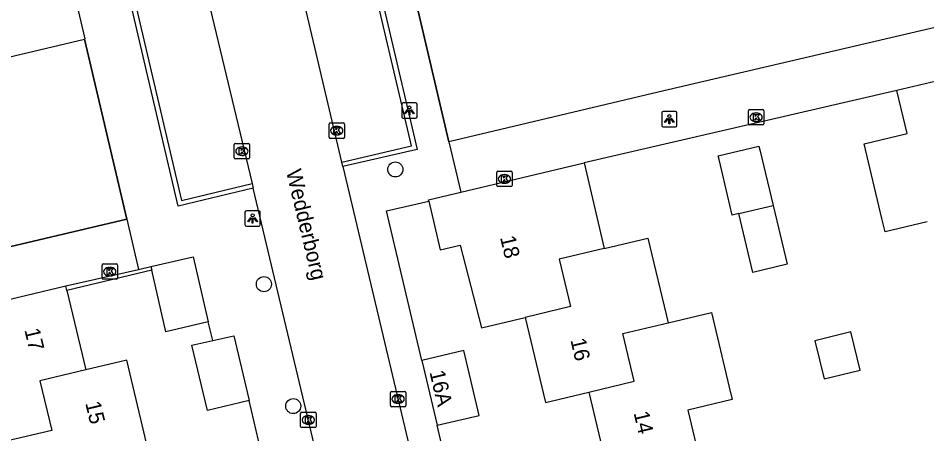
# Model space of a CAD drawing. Extents: x 158038 to 159242, y 380133 to 381214.
# Drawn here: x 158907 to 158966.1, y 380537.7 to 380564.7 of the extents above; entities that cross this region are included whole.
import ezdxf

# ---------------------------------------------------------------- set-up
doc = ezdxf.new("R2010")
doc.units = 0
for name, color, linetype in [('IMGEO_Boom', 7, 'Continuous'), ('IMGEO_Kolk', 7, 'Continuous'), ('IMGEO_Lichtpunt', 7, 'Continuous'), ('IMGEO_Muur', 7, 'Continuous'), ('IMGEO_Openbare_ruimte_label', 7, 'Continuous'), ('IMGEO_Pand', 7, 'Continuous'), ('IMGEO_Pand_nummerreeks', 7, 'Continuous'), ('IMGEO_Rijbaan_lokaal_open', 7, 'Continuous'), ('IMGEO_Voetpad_open', 7, 'Continuous')]:
    doc.layers.add(name, color=color, linetype=linetype)

msp = doc.modelspace()

# ---------------------------------------------------------------- linework, layer by layer
at = {"layer": 'IMGEO_Boom'}
for centre in [(158931.531, 380554.881), (158922.981, 380547.417), (158924.892, 380539.482)]:
    msp.add_circle(centre, 0.489, dxfattribs=at)
at = {"layer": 'IMGEO_Kolk'}
for p, q in [((158954.576, 380558.78), (158955.428, 380558.78)), ((158954.501, 380557.854), (158954.501, 380558.706)), ((158954.989, 380558.56), (158955.014, 380558.56)), ((158955.502, 380558.706), (158955.502, 380557.854)), ((158927.218, 380556.98), (158927.218, 380557.832)), ((158927.293, 380557.906), (158928.145, 380557.906)), ((158927.706, 380557.686), (158927.731, 380557.686)), ((158928.219, 380557.832), (158928.219, 380556.98)), ((158955.428, 380557.78), (158954.576, 380557.78)), ((158955.012, 380558), (158954.987, 380558)), ((158927.729, 380557.126), (158927.704, 380557.126)), ((158921.052, 380555.644), (158921.052, 380556.496)), ((158921.127, 380556.57), (158921.979, 380556.57)), ((158922.053, 380556.496), (158922.053, 380555.644)), ((158928.145, 380556.906), (158927.293, 380556.906)), ((158921.54, 380556.35), (158921.565, 380556.35)), ((158921.979, 380555.57), (158921.127, 380555.57)), ((158921.563, 380555.79), (158921.538, 380555.79)), ((158938.127, 380553.838), (158938.127, 380554.69)), ((158938.202, 380554.764), (158939.054, 380554.764)), ((158939.128, 380554.69), (158939.128, 380553.838)), ((158938.615, 380554.544), (158938.64, 380554.544)), ((158939.054, 380553.764), (158938.202, 380553.764)), ((158938.638, 380553.984), (158938.613, 380553.984)), ((158912.533, 380548.731), (158913.385, 380548.731)), ((158912.458, 380547.805), (158912.458, 380548.657)), ((158912.946, 380548.511), (158912.971, 380548.511)), ((158913.459, 380548.657), (158913.459, 380547.805)), ((158913.385, 380547.731), (158912.533, 380547.731)), ((158912.969, 380547.951), (158912.944, 380547.951)), ((158931.285, 380540.441), (158932.137, 380540.441)), ((158931.21, 380539.515), (158931.21, 380540.367)), ((158931.698, 380540.221), (158931.723, 380540.221)), ((158932.211, 380540.367), (158932.211, 380539.515)), ((158932.137, 380539.441), (158931.285, 380539.441)), ((158931.721, 380539.661), (158931.696, 380539.661)), ((158925.371, 380538.154), (158925.371, 380539.006)), ((158925.446, 380539.08), (158926.298, 380539.08)), ((158925.859, 380538.86), (158925.884, 380538.86)), ((158926.372, 380539.006), (158926.372, 380538.154)), ((158926.298, 380538.08), (158925.446, 380538.08)), ((158925.882, 380538.3), (158925.857, 380538.3))]:
    msp.add_line(p, q, dxfattribs=at)
for points in [[(158954.576, 380558.78), (158955.428, 380558.78)], [(158954.501, 380557.854), (158954.501, 380558.706)], [(158954.822, 380558.48), (158954.945, 380558.48), (158954.945, 380558.329), (158955.075, 380558.48), (158955.239, 380558.48), (158955.093, 380558.329), (158955.246, 380558.08), (158955.094, 380558.08), (158955.009, 380558.244), (158954.945, 380558.177), (158954.945, 380558.08), (158954.822, 380558.08), (158954.822, 380558.48)], [(158955.502, 380558.706), (158955.502, 380557.854)], [(158927.218, 380556.98), (158927.218, 380557.832)], [(158927.293, 380557.906), (158928.145, 380557.906)], [(158927.539, 380557.606), (158927.662, 380557.606), (158927.662, 380557.455), (158927.792, 380557.606), (158927.956, 380557.606), (158927.81, 380557.455), (158927.963, 380557.206), (158927.811, 380557.206), (158927.726, 380557.37), (158927.662, 380557.303), (158927.662, 380557.206), (158927.539, 380557.206), (158927.539, 380557.606)], [(158928.219, 380557.832), (158928.219, 380556.98)], [(158955.428, 380557.78), (158954.576, 380557.78)], [(158921.052, 380555.644), (158921.052, 380556.496)], [(158921.127, 380556.57), (158921.979, 380556.57)], [(158922.053, 380556.496), (158922.053, 380555.644)], [(158928.145, 380556.906), (158927.293, 380556.906)], [(158921.373, 380556.27), (158921.496, 380556.27), (158921.496, 380556.119), (158921.626, 380556.27), (158921.79, 380556.27), (158921.644, 380556.119), (158921.797, 380555.87), (158921.645, 380555.87), (158921.56, 380556.034), (158921.496, 380555.967), (158921.496, 380555.87), (158921.373, 380555.87), (158921.373, 380556.27)], [(158921.979, 380555.57), (158921.127, 380555.57)], [(158938.127, 380553.838), (158938.127, 380554.69)], [(158938.202, 380554.764), (158939.054, 380554.764)], [(158939.128, 380554.69), (158939.128, 380553.838)], [(158938.448, 380554.464), (158938.571, 380554.464), (158938.571, 380554.313), (158938.701, 380554.464), (158938.865, 380554.464), (158938.719, 380554.313), (158938.872, 380554.064), (158938.72, 380554.064), (158938.635, 380554.228), (158938.571, 380554.161), (158938.571, 380554.064), (158938.448, 380554.064), (158938.448, 380554.464)], [(158939.054, 380553.764), (158938.202, 380553.764)], [(158912.533, 380548.731), (158913.385, 380548.731)], [(158912.458, 380547.805), (158912.458, 380548.657)], [(158912.779, 380548.431), (158912.902, 380548.431), (158912.902, 380548.28), (158913.032, 380548.431), (158913.196, 380548.431), (158913.05, 380548.28), (158913.203, 380548.031), (158913.051, 380548.031), (158912.966, 380548.195), (158912.902, 380548.128), (158912.902, 380548.031), (158912.779, 380548.031), (158912.779, 380548.431)], [(158913.459, 380548.657), (158913.459, 380547.805)], [(158913.385, 380547.731), (158912.533, 380547.731)], [(158931.285, 380540.441), (158932.137, 380540.441)], [(158931.21, 380539.515), (158931.21, 380540.367)], [(158931.531, 380540.141), (158931.654, 380540.141), (158931.654, 380539.99), (158931.784, 380540.141), (158931.948, 380540.141), (158931.802, 380539.99), (158931.955, 380539.741), (158931.803, 380539.741), (158931.718, 380539.905), (158931.654, 380539.838), (158931.654, 380539.741), (158931.531, 380539.741), (158931.531, 380540.141)], [(158932.211, 380540.367), (158932.211, 380539.515)], [(158932.137, 380539.441), (158931.285, 380539.441)], [(158925.371, 380538.154), (158925.371, 380539.006)], [(158925.446, 380539.08), (158926.298, 380539.08)], [(158925.692, 380538.78), (158925.815, 380538.78), (158925.815, 380538.629), (158925.945, 380538.78), (158926.109, 380538.78), (158925.963, 380538.629), (158926.116, 380538.38), (158925.964, 380538.38), (158925.879, 380538.544), (158925.815, 380538.477), (158925.815, 380538.38), (158925.692, 380538.38), (158925.692, 380538.78)], [(158926.372, 380539.006), (158926.372, 380538.154)], [(158926.298, 380538.08), (158925.446, 380538.08)]]:
    msp.add_lwpolyline(points, dxfattribs=at)
for centre, start, end in [((158954.578, 380558.704), 91.55205, 178.44795), ((158954.578, 380558.704), 91.55205, 178.44795), ((158955.426, 380558.704), 1.55205, 88.44795), ((158955.426, 380558.704), 1.55205, 88.44795), ((158927.295, 380557.83), 91.55205, 178.44795), ((158927.295, 380557.83), 91.55205, 178.44795), ((158928.143, 380557.83), 1.55205, 88.44795), ((158928.143, 380557.83), 1.55205, 88.44795), ((158954.578, 380557.856), 181.55205, 268.44795), ((158954.578, 380557.856), 181.55205, 268.44795), ((158955.426, 380557.856), 271.55205, 358.44795), ((158955.426, 380557.856), 271.55205, 358.44795), ((158921.129, 380556.494), 91.55205, 178.44795), ((158921.129, 380556.494), 91.55205, 178.44795), ((158921.977, 380556.494), 1.55205, 88.44795), ((158921.977, 380556.494), 1.55205, 88.44795), ((158927.295, 380556.982), 181.55205, 268.44795), ((158927.295, 380556.982), 181.55205, 268.44795), ((158928.143, 380556.982), 271.55205, 358.44795), ((158928.143, 380556.982), 271.55205, 358.44795), ((158921.129, 380555.646), 181.55205, 268.44795), ((158921.129, 380555.646), 181.55205, 268.44795), ((158921.977, 380555.646), 271.55205, 358.44795), ((158921.977, 380555.646), 271.55205, 358.44795), ((158938.204, 380554.688), 91.55205, 178.44795), ((158938.204, 380554.688), 91.55205, 178.44795), ((158939.052, 380554.688), 1.55205, 88.44795), ((158939.052, 380554.688), 1.55205, 88.44795), ((158938.204, 380553.84), 181.55205, 268.44795), ((158938.204, 380553.84), 181.55205, 268.44795), ((158939.052, 380553.84), 271.55205, 358.44795), ((158939.052, 380553.84), 271.55205, 358.44795), ((158912.535, 380548.655), 91.55205, 178.44795), ((158912.535, 380548.655), 91.55205, 178.44795), ((158913.383, 380548.655), 1.55205, 88.44795), ((158913.383, 380548.655), 1.55205, 88.44795), ((158912.535, 380547.807), 181.55205, 268.44795), ((158912.535, 380547.807), 181.55205, 268.44795), ((158913.383, 380547.807), 271.55205, 358.44795), ((158913.383, 380547.807), 271.55205, 358.44795), ((158931.287, 380540.365), 91.55205, 178.44795), ((158931.287, 380540.365), 91.55205, 178.44795), ((158932.135, 380540.365), 1.55205, 88.44795), ((158932.135, 380540.365), 1.55205, 88.44795), ((158931.287, 380539.517), 181.55205, 268.44795), ((158931.287, 380539.517), 181.55205, 268.44795), ((158932.135, 380539.517), 271.55205, 358.44795), ((158932.135, 380539.517), 271.55205, 358.44795), ((158925.448, 380539.004), 91.55205, 178.44795), ((158925.448, 380539.004), 91.55205, 178.44795), ((158926.296, 380539.004), 1.55205, 88.44795), ((158926.296, 380539.004), 1.55205, 88.44795), ((158925.448, 380538.156), 181.55205, 268.44795), ((158925.448, 380538.156), 181.55205, 268.44795), ((158926.296, 380538.156), 271.55205, 358.44795), ((158926.296, 380538.156), 271.55205, 358.44795)]:
    msp.add_arc(centre, 0.0765, start, end, dxfattribs=at)
for centre, major_axis, ratio, start_param, end_param in [((158954.988, 380558.28), (-0.387, 0.002), 0.722429, 4.712389, 7.853982), ((158955.013, 380558.28), (-0.39, 0.002), 0.717154, 1.570796, 4.712389), ((158927.705, 380557.406), (-0.387, 0.002), 0.722429, 4.712389, 7.853982), ((158927.73, 380557.406), (-0.39, 0.002), 0.717154, 1.570796, 4.712389), ((158921.539, 380556.07), (-0.387, 0.002), 0.722429, 4.712389, 7.853982), ((158921.564, 380556.07), (-0.39, 0.002), 0.717154, 1.570796, 4.712389), ((158938.614, 380554.264), (-0.387, 0.002), 0.722429, 4.712389, 7.853982), ((158938.639, 380554.264), (-0.39, 0.002), 0.717154, 1.570796, 4.712389), ((158912.945, 380548.231), (-0.387, 0.002), 0.722429, 4.712389, 7.853982), ((158912.97, 380548.231), (-0.39, 0.002), 0.717154, 1.570796, 4.712389), ((158931.697, 380539.941), (-0.387, 0.002), 0.722429, 4.712389, 7.853982), ((158931.722, 380539.941), (-0.39, 0.002), 0.717154, 1.570796, 4.712389), ((158925.858, 380538.58), (-0.387, 0.002), 0.722429, 4.712389, 7.853982), ((158925.883, 380538.58), (-0.39, 0.002), 0.717154, 1.570796, 4.712389)]:
    msp.add_ellipse(centre, major_axis=major_axis, ratio=ratio, start_param=start_param, end_param=end_param, dxfattribs=at)
at = {"layer": 'IMGEO_Lichtpunt'}
for p, q in [((158931.948, 380559.12), (158931.948, 380558.313)), ((158931.948, 380559.12), (158931.948, 380558.313)), ((158932.85, 380559.215), (158932.042, 380559.215)), ((158932.85, 380559.215), (158932.042, 380559.215)), ((158932.944, 380558.313), (158932.944, 380559.12)), ((158932.944, 380558.313), (158932.944, 380559.12)), ((158932.042, 380558.219), (158932.85, 380558.219)), ((158932.042, 380558.219), (158932.85, 380558.219)), ((158948.859, 380558.556), (158948.859, 380557.749)), ((158948.859, 380558.556), (158948.859, 380557.749)), ((158949.761, 380558.651), (158948.953, 380558.651)), ((158949.761, 380558.651), (158948.953, 380558.651)), ((158949.855, 380557.749), (158949.855, 380558.556)), ((158949.855, 380557.749), (158949.855, 380558.556)), ((158948.953, 380557.655), (158949.761, 380557.655)), ((158948.953, 380557.655), (158949.761, 380557.655)), ((158921.749, 380552.097), (158921.749, 380551.29)), ((158921.749, 380552.097), (158921.749, 380551.29)), ((158922.651, 380552.192), (158921.843, 380552.192)), ((158922.651, 380552.192), (158921.843, 380552.192)), ((158922.745, 380551.29), (158922.745, 380552.097)), ((158922.745, 380551.29), (158922.745, 380552.097)), ((158921.843, 380551.196), (158922.651, 380551.196)), ((158921.843, 380551.196), (158922.651, 380551.196))]:
    msp.add_line(p, q, dxfattribs=at)
for points in [[(158932.322, 380558.784), (158932.361, 380558.756), (158932.173, 380558.494), (158932.135, 380558.521), (158932.322, 380558.784)], [(158932.534, 380558.756), (158932.572, 380558.783), (158932.759, 380558.521), (158932.72, 380558.493), (158932.534, 380558.756)], [(158932.424, 380558.736), (158932.471, 380558.736), (158932.471, 380558.414), (158932.424, 380558.414), (158932.424, 380558.736)], [(158949.233, 380558.22), (158949.272, 380558.192), (158949.084, 380557.93), (158949.046, 380557.957), (158949.233, 380558.22)], [(158949.445, 380558.192), (158949.483, 380558.219), (158949.67, 380557.957), (158949.631, 380557.929), (158949.445, 380558.192)], [(158949.335, 380558.172), (158949.382, 380558.172), (158949.382, 380557.85), (158949.335, 380557.85), (158949.335, 380558.172)], [(158922.123, 380551.761), (158922.162, 380551.733), (158921.974, 380551.471), (158921.936, 380551.498), (158922.123, 380551.761)], [(158922.225, 380551.713), (158922.272, 380551.713), (158922.272, 380551.391), (158922.225, 380551.391), (158922.225, 380551.713)], [(158922.335, 380551.733), (158922.373, 380551.76), (158922.56, 380551.498), (158922.521, 380551.47), (158922.335, 380551.733)]]:
    msp.add_lwpolyline(points, dxfattribs=at)
for centre in [(158932.447, 380558.918), (158949.358, 380558.354), (158922.248, 380551.895)]:
    msp.add_circle(centre, 0.0994, dxfattribs=at)
for centre, start, end in [((158932.042, 380559.12), 90, 180), ((158932.042, 380559.12), 90, 180), ((158932.85, 380559.12), 0, 90), ((158932.85, 380559.12), 0, 90), ((158932.042, 380558.313), 180, 270), ((158932.042, 380558.313), 180, 270), ((158932.85, 380558.313), 270, 0), ((158932.85, 380558.313), 270, 360), ((158948.953, 380558.556), 90, 180), ((158948.953, 380558.556), 90, 180), ((158949.761, 380558.556), 0, 90), ((158949.761, 380558.556), 0, 90), ((158948.953, 380557.749), 180, 270), ((158948.953, 380557.749), 180, 270), ((158949.761, 380557.749), 270, 0), ((158949.761, 380557.749), 270, 360), ((158921.843, 380552.097), 90, 180), ((158921.843, 380552.097), 90, 180), ((158922.651, 380552.097), 0, 90), ((158922.651, 380552.097), 0, 90), ((158921.843, 380551.29), 180, 270), ((158921.843, 380551.29), 180, 270), ((158922.651, 380551.29), 270, 0), ((158922.651, 380551.29), 270, 360)]:
    msp.add_arc(centre, 0.0946, start, end, dxfattribs=at)
at = {"layer": 'IMGEO_Muur'}
for points in [[(158923.12, 380576.294), (158927.96, 380577.456), (158932.954, 380556.187), (158928.109, 380555.067)], [(158928.042, 380555.359), (158932.593, 380556.411), (158927.737, 380577.094), (158923.19, 380576.002)], [(158922.291, 380553.668), (158917.397, 380552.495), (158912.429, 380573.742), (158917.211, 380574.887)], [(158917.281, 380574.595), (158912.789, 380573.52), (158917.62, 380552.857), (158922.221, 380553.959)], [(158935.017, 380556.675), (158932.272, 380568.344)], [(158911.308, 380563.353), (158914.062, 380551.644)], [(158948.632, 380559.912), (158935.017, 380556.675)], [(158928.109, 380555.067), (158928.042, 380555.359)], [(158922.221, 380553.959), (158922.291, 380553.668)], [(158914.062, 380551.644), (158867.216, 380540.609)], [(158910.093, 380547.302), (158914.831, 380548.377)], [(158915.689, 380548.326), (158910.165, 380547.001)], [(158914.831, 380548.377), (158915.633, 380548.559)]]:
    msp.add_lwpolyline(points, dxfattribs=at)
at = {"layer": 'IMGEO_Pand'}
for points in [[(158911.308, 380563.353), (158911.362, 380563.372), (158908.979, 380573.524)], [(158905.909, 380562.085), (158911.308, 380563.353)], [(158970.046, 380561.405), (158964.159, 380560.013)], [(158966.13, 380551.476), (158963.39, 380550.828), (158963.186, 380551.691), (158962.035, 380556.556), (158964.821, 380557.215), (158964.159, 380560.013)], [(158953.885, 380552.019), (158953.449, 380551.915), (158952.677, 380555.16), (158952.59, 380555.526), (158952.532, 380555.772), (158955.184, 380556.403), (158955.243, 380556.156), (158956.102, 380552.546)], [(158935.787, 380553.4), (158943.807, 380555.305)], [(158943.807, 380555.305), (158945.128, 380549.74)], [(158933.703, 380552.822), (158933.687, 380552.901), (158935.787, 380553.4)], [(158933.703, 380552.822), (158934.454, 380549.656), (158935.747, 380549.963), (158937.146, 380544.582), (158939.975, 380545.255)], [(158956.102, 380552.546), (158957.013, 380548.711), (158954.797, 380548.184), (158953.885, 380552.019)], [(158953.885, 380552.019), (158956.102, 380552.546)], [(158945.128, 380549.74), (158947.962, 380550.414), (158949.273, 380544.901)], [(158945.128, 380549.74), (158942.201, 380549.044), (158942.935, 380545.959), (158939.975, 380545.255)], [(158915.633, 380548.559), (158918.381, 380549.198), (158919.356, 380544.957)], [(158915.633, 380548.559), (158915.689, 380548.326)], [(158919.356, 380544.957), (158916.609, 380544.319), (158915.689, 380548.326)], [(158904, 380545.853), (158910.093, 380547.302)], [(158910.165, 380547.001), (158910.093, 380547.302)], [(158910.165, 380547.001), (158911.392, 380541.842)], [(158939.975, 380545.255), (158941.292, 380539.72), (158944.115, 380540.392)], [(158949.273, 380544.901), (158952.103, 380545.574), (158953.26, 380540.71), (158953.452, 380539.903), (158950.57, 380539.217), (158951.22, 380536.483)], [(158944.115, 380540.392), (158947.064, 380541.094), (158946.325, 380544.2), (158949.273, 380544.901)], [(158919.652, 380543.746), (158921.033, 380544.064), (158922.031, 380539.837)], [(158961.158, 380544.309), (158958.828, 380543.735), (158959.439, 380541.251), (158961.769, 380541.825), (158961.158, 380544.309)], [(158922.031, 380539.837), (158919.306, 380539.194), (158918.304, 380543.437), (158919.652, 380543.746)], [(158934.257, 380538.231), (158936.982, 380538.875), (158935.982, 380543.103), (158933.257, 380542.459)], [(158915.374, 380536.973), (158914.059, 380542.479), (158911.392, 380541.842)], [(158933.257, 380542.459), (158934.257, 380538.231)], [(158911.392, 380541.842), (158908.413, 380541.13), (158909.185, 380537.902), (158906.209, 380537.191)], [(158944.115, 380540.392), (158945.377, 380535.085)]]:
    msp.add_lwpolyline(points, dxfattribs=at)
at = {"layer": 'IMGEO_Rijbaan_lokaal_open'}
for points in [[(158928.042, 380555.359), (158923.19, 380576.002)], [(158917.281, 380574.595), (158922.221, 380553.959)], [(158928.109, 380555.067), (158933.156, 380533.858)], [(158927.337, 380532.423), (158922.291, 380553.668)]]:
    msp.add_lwpolyline(points, dxfattribs=at)
at = {"layer": 'IMGEO_Voetpad_open'}
for points in [[(158970.916, 380577.581), (158973.618, 380565.749), (158948.632, 380559.912), (158935.017, 380556.675)], [(158932.272, 380568.344), (158935.017, 380556.675)], [(158914.062, 380551.644), (158911.308, 380563.353)], [(158964.159, 380560.013), (158943.807, 380555.305)], [(158935.017, 380556.675), (158935.787, 380553.4)], [(158933.257, 380542.459), (158930.962, 380552.18), (158933.703, 380552.822)], [(158873.168, 380515.298), (158867.216, 380540.609), (158914.062, 380551.644)], [(158914.062, 380551.644), (158914.831, 380548.377)], [(158919.652, 380543.746), (158919.356, 380544.957)], [(158923.23, 380534.648), (158922.031, 380539.837)], [(158934.545, 380537.029), (158934.257, 380538.231)]]:
    msp.add_lwpolyline(points, dxfattribs=at)

# ---------------------------------------------------------------- texts
at = {"layer": 'IMGEO_Openbare_ruimte_label'}
msp.add_text('Wedderborg', height=1, rotation=283.41107, dxfattribs=at).set_placement((158924.418, 380554.758))
at = {"layer": 'IMGEO_Pand_nummerreeks'}
for s, rotation, p in [('18', 283.37626, (158938.339, 380550.46)), ('17', 283.43103, (158907.396, 380544.441)), ('16', 283.3841, (158942.915, 380543.786)), ('16A', 283.3829, (158933.745, 380541.697)), ('15', 283.43235, (158911.356, 380539.679)), ('14', 283.37644, (158947.027, 380539.036))]:
    msp.add_text(s, height=1, rotation=rotation, dxfattribs=at).set_placement(p)

doc.saveas('drawing.dxf')
